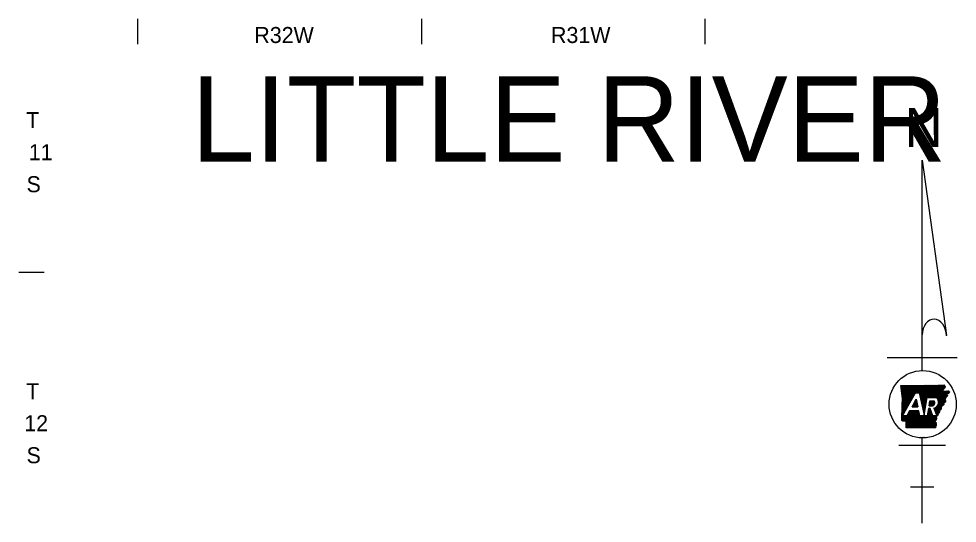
# Model space of a CAD drawing. Extents: x -17742 to 32032, y -17264 to 5867.
# Drawn here: x 27246 to 30763, y 3876 to 5766 of the extents above; entities that cross this region are included whole.
import ezdxf

# ---------------------------------------------------------------- set-up
doc = ezdxf.new("R2010")
doc.units = 0
for name, color, linetype in [('2', 7, 'Continuous'), ('Default', 7, 'Continuous'), ('R_Annotation', 7, 'Continuous')]:
    doc.layers.add(name, color=color, linetype=linetype)

msp = doc.modelspace()

# ---------------------------------------------------------------- linework, layer by layer
at = {"layer": 'Default'}
for p, q in [((27691.2, 5765.9), (27691.2, 5670.9)), ((28755.6, 5765.9), (28755.6, 5670.9)), ((29817.5, 5765.9), (29817.5, 5670.9)), ((27340.7, 4814.8), (27245.7, 4814.8))]:
    msp.add_line(p, q, dxfattribs=at)
at = {"layer": 'R_Annotation'}
for p, q in [((30631.7, 5235.8), (30722.6, 4578.7)), ((30631.7, 4447.8), (30631.7, 5235.8)), ((30500.1, 4496.6), (30763.3, 4496.6)), ((30551.9, 4391.4), (30553, 4392.5)), ((30552.3, 4388.3), (30556.5, 4392.5)), ((30552.7, 4385.2), (30559.9, 4392.5)), ((30553.1, 4382.1), (30563.4, 4392.5)), ((30553.4, 4379), (30566.9, 4392.5)), ((30553.8, 4375.9), (30570.4, 4392.5)), ((30554.2, 4372.8), (30573.9, 4392.5)), ((30554.6, 4369.7), (30577.3, 4392.5)), ((30555, 4366.6), (30580.8, 4392.5)), ((30555.4, 4363.5), (30584.3, 4392.5)), ((30555.8, 4360.4), (30587.8, 4392.5)), ((30556.1, 4357.3), (30591.3, 4392.5)), ((30556.5, 4354.2), (30594.8, 4392.5)), ((30556.9, 4351.1), (30598.2, 4392.5)), ((30557, 4316.4), (30633.1, 4392.5)), ((30557.1, 4320), (30629.6, 4392.5)), ((30557.3, 4323.6), (30626.2, 4392.5)), ((30557.3, 4348), (30601.7, 4392.5)), ((30557.4, 4327.2), (30622.7, 4392.5)), ((30557.5, 4330.8), (30619.2, 4392.5)), ((30557.6, 4334.4), (30615.7, 4392.5)), ((30557.7, 4338), (30612.2, 4392.5)), ((30557.7, 4344.9), (30605.2, 4392.5)), ((30557.9, 4341.6), (30608.7, 4392.5)), ((30558.1, 4278.9), (30606.6, 4364.7)), ((30606.6, 4364.7), (30621.1, 4364.7)), ((30608.8, 4364.7), (30636.6, 4392.5)), ((30612.2, 4364.7), (30640.1, 4392.5)), ((30615.7, 4364.7), (30643.6, 4392.6)), ((30619.2, 4364.7), (30647.2, 4392.6)), ((30621.4, 4363.4), (30650.7, 4392.7)), ((30622, 4360.5), (30654.2, 4392.7)), ((30622.6, 4357.6), (30657.8, 4392.8)), ((30623.2, 4354.7), (30661.3, 4392.8)), ((30623.8, 4351.9), (30664.9, 4392.9)), ((30624.4, 4349), (30668.4, 4393)), ((30625.1, 4346.1), (30671.9, 4393)), ((30625.7, 4343.3), (30675.5, 4393.1)), ((30626.3, 4340.4), (30679, 4393.1)), ((30626.9, 4337.5), (30682.5, 4393.2)), ((30627.5, 4334.7), (30686.1, 4393.2)), ((30628.1, 4331.8), (30689.6, 4393.3)), ((30628.7, 4328.9), (30693.2, 4393.4)), ((30629.3, 4326.1), (30696.7, 4393.4)), ((30653.5, 4346.8), (30700.3, 4393.5)), ((30657, 4346.8), (30703.9, 4393.6)), ((30660.5, 4346.8), (30707.4, 4393.7)), ((30664, 4346.8), (30711, 4393.8)), ((30667.5, 4346.8), (30714.6, 4393.8)), ((30671, 4346.8), (30715.3, 4391.1)), ((30674.4, 4346.8), (30717, 4389.3)), ((30677.9, 4346.8), (30717.5, 4386.3)), ((30681.4, 4346.8), (30709.5, 4374.9)), ((30684.6, 4346.4), (30708.8, 4370.7)), ((30686.5, 4344.9), (30712.5, 4370.9)), ((30688.2, 4343.1), (30716.2, 4371.1)), ((30689.7, 4341.1), (30719.8, 4371.3)), ((30691, 4338.9), (30723.5, 4371.5)), ((30692, 4336.5), (30727.2, 4371.7)), ((30692.8, 4333.8), (30730.5, 4371.5)), ((30693.3, 4330.8), (30732.1, 4369.6)), ((30730.6, 4364.6), (30733.7, 4367.8)), ((30556.4, 4298.4), (30585.7, 4327.7)), ((30556.6, 4302), (30590.3, 4335.7)), ((30556.7, 4305.6), (30594.8, 4343.8)), ((30556.8, 4309.2), (30599.4, 4351.8)), ((30556.9, 4312.8), (30603.9, 4359.8)), ((30593.8, 4312.5), (30609.7, 4340.6)), ((30594, 4312.5), (30611.9, 4330.4)), ((30597.5, 4312.5), (30612.5, 4327.6)), ((30598.1, 4320.2), (30611.3, 4333.3)), ((30602.7, 4328.2), (30610.6, 4336.2)), ((30607.2, 4336.2), (30610, 4339)), ((30630, 4323.2), (30649.7, 4342.9)), ((30630.6, 4320.3), (30649, 4338.7)), ((30631.2, 4317.4), (30648.3, 4334.5)), ((30631.8, 4314.6), (30647.5, 4330.3)), ((30650.4, 4346.8), (30684.1, 4346.8)), ((30657.7, 4316.3), (30676.1, 4334.7)), ((30658.4, 4320.5), (30672.6, 4334.7)), ((30659.2, 4324.7), (30669.1, 4334.7)), ((30659.9, 4329), (30665.6, 4334.7)), ((30660.7, 4333.2), (30662.1, 4334.7)), ((30660.9, 4334.7), (30676.8, 4334.7)), ((30661.2, 4316.3), (30678, 4333.1)), ((30664.7, 4316.3), (30679.2, 4330.8)), ((30668.2, 4316.3), (30679.8, 4328)), ((30678.2, 4301.8), (30716.8, 4340.4)), ((30679.2, 4299.2), (30717.5, 4337.6)), ((30680.1, 4296.7), (30718.1, 4334.7)), ((30681, 4294.2), (30718.8, 4331.9)), ((30689.6, 4316.6), (30716.2, 4343.2)), ((30692.6, 4323.1), (30724.2, 4354.7)), ((30693.3, 4327.3), (30723.8, 4357.8)), ((30720.3, 4347.4), (30724.6, 4351.7)), ((30556, 4284), (30567.5, 4295.6)), ((30556.1, 4287.6), (30572.1, 4303.6)), ((30556.2, 4291.2), (30576.6, 4311.6)), ((30556.3, 4294.8), (30581.2, 4319.7)), ((30556.6, 4260.3), (30593.2, 4296.9)), ((30558.7, 4258.8), (30596.7, 4296.9)), ((30561.2, 4257.9), (30600.2, 4296.9)), ((30565.3, 4258.5), (30603.6, 4296.9)), ((30568.8, 4258.6), (30607.1, 4296.9)), ((30571.6, 4257.8), (30610.6, 4296.9)), ((30571.7, 4251), (30617.6, 4296.9)), ((30571.7, 4254.5), (30614.1, 4296.9)), ((30571.7, 4247.5), (30619.4, 4295.2)), ((30571.7, 4244), (30620, 4292.3)), ((30584.9, 4296.9), (30574.7, 4278.9)), ((30578.7, 4285.8), (30589.7, 4296.9)), ((30583.2, 4293.9), (30586.2, 4296.9)), ((30619.1, 4296.9), (30584.9, 4296.9)), ((30593.8, 4312.5), (30615.7, 4312.5)), ((30600.9, 4312.5), (30613.1, 4324.7)), ((30604.4, 4312.5), (30613.7, 4321.8)), ((30606.6, 4233.6), (30666.5, 4293.5)), ((30607.9, 4312.5), (30614.3, 4319)), ((30611.4, 4312.5), (30614.9, 4316.1)), ((30614.9, 4312.5), (30615.6, 4313.2)), ((30632.4, 4311.7), (30646.8, 4326.1)), ((30633, 4308.8), (30646.1, 4321.9)), ((30633.6, 4306), (30645.3, 4317.6)), ((30634.3, 4303.1), (30644.6, 4313.4)), ((30634.9, 4300.2), (30643.8, 4309.2)), ((30635.5, 4297.4), (30643.1, 4305)), ((30636.1, 4294.5), (30642.4, 4300.8)), ((30636.7, 4291.6), (30641.6, 4296.6)), ((30637.3, 4288.8), (30640.9, 4292.3)), ((30651.8, 4282.3), (30665.5, 4296)), ((30652.5, 4286.5), (30664.6, 4298.6)), ((30653.3, 4290.8), (30663.6, 4301.1)), ((30654, 4295), (30662.7, 4303.7)), ((30654.7, 4299.2), (30661.7, 4306.2)), ((30655.5, 4303.4), (30658.2, 4306.2)), ((30661.8, 4306.2), (30655.9, 4306.2)), ((30657.7, 4316.3), (30672.2, 4316.3)), ((30671.9, 4278.9), (30661.8, 4306.2)), ((30671.7, 4316.3), (30679.5, 4324.2)), ((30676.1, 4307.6), (30686.7, 4278.9)), ((30676.3, 4306.9), (30677.4, 4307.9)), ((30677.3, 4304.3), (30683.9, 4311)), ((30682, 4291.6), (30702.9, 4312.5)), ((30682.9, 4289.1), (30702.5, 4308.6)), ((30683.9, 4286.5), (30702.1, 4304.8)), ((30684.8, 4284), (30695.5, 4294.7)), ((30706.9, 4316.5), (30711.8, 4321.4)), ((30555.3, 4262.4), (30571.7, 4278.9)), ((30555.4, 4266), (30568.2, 4278.9)), ((30555.5, 4269.6), (30564.7, 4278.9)), ((30555.6, 4273.2), (30561.3, 4278.9)), ((30555.7, 4276.8), (30558.4, 4279.5)), ((30555.8, 4280.4), (30563, 4287.6)), ((30574.7, 4278.9), (30558.1, 4278.9)), ((30571.7, 4240.6), (30620.6, 4289.5)), ((30571.7, 4237.1), (30621.3, 4286.6)), ((30571.8, 4233.7), (30621.9, 4283.7)), ((30575.3, 4233.7), (30622.5, 4280.9)), ((30578.7, 4233.6), (30624, 4278.9)), ((30582.2, 4233.6), (30627.4, 4278.9)), ((30585.7, 4233.6), (30630.9, 4278.9)), ((30589.2, 4233.6), (30634.4, 4278.9)), ((30592.6, 4233.6), (30637.9, 4278.9)), ((30596.1, 4233.6), (30641.4, 4278.9)), ((30599.6, 4233.6), (30644.8, 4278.9)), ((30603.1, 4233.6), (30648.3, 4278.9)), ((30610, 4233.6), (30667.4, 4291)), ((30613.5, 4233.6), (30668.3, 4288.4)), ((30617, 4233.6), (30669.3, 4285.9)), ((30620.5, 4233.6), (30670.2, 4283.3)), ((30651.2, 4278.9), (30622.9, 4278.9)), ((30623.9, 4233.6), (30671.2, 4280.8)), ((30627.4, 4233.6), (30672.7, 4278.9)), ((30630.9, 4233.6), (30676.2, 4278.9)), ((30634.4, 4233.6), (30679.7, 4278.9)), ((30637.8, 4233.6), (30683.2, 4278.9)), ((30637.9, 4285.9), (30640.2, 4288.1)), ((30638.6, 4283), (30639.4, 4283.9)), ((30641.3, 4233.5), (30684.3, 4276.5)), ((30644.8, 4233.5), (30684.5, 4273.2)), ((30648.3, 4233.5), (30684.6, 4269.9)), ((30651.8, 4233.5), (30684.8, 4266.6)), ((30655.2, 4233.5), (30679.1, 4257.4)), ((30686.7, 4278.9), (30671.9, 4278.9)), ((30685.7, 4281.4), (30694, 4289.7)), ((30658.7, 4233.5), (30680.1, 4255)), ((30662.2, 4233.5), (30681.2, 4252.5)), ((30665.7, 4233.5), (30682.3, 4250.1)), ((30669.1, 4233.5), (30683.4, 4247.7)), ((30672.6, 4233.5), (30684.3, 4245.1)), ((30676.1, 4233.5), (30682.7, 4240.1)), ((30679.6, 4233.5), (30681.1, 4235)), ((30631.7, 3876), (30631.7, 4195.8)), ((30544, 4168.6), (30719.4, 4168.6)), ((30587.9, 4012.8), (30675.6, 4012.8))]:
    msp.add_line(p, q, dxfattribs=at)
for points in [[(30551.8, 4392.5), (30599.8, 4392.5), (30642, 4392.5), (30691.7, 4393.3), (30714.8, 4393.9)], [(30551.8, 4392.5), (30599.8, 4392.5), (30642, 4392.5), (30691.7, 4393.3), (30714.8, 4393.9)], [(30557.1, 4317.8), (30557.9, 4343.1), (30551.8, 4392.5)], [(30555.2, 4262.5), (30557.9, 4343.1), (30551.8, 4392.5)], [(30621.1, 4364.7), (30639, 4281.2), (30650.4, 4346.8)], [(30729.9, 4371.8), (30734, 4367.4), (30723.7, 4358.9), (30724.8, 4350.3), (30715.9, 4344.4), (30718.9, 4331.2), (30712.1, 4325), (30711.5, 4318.2), (30703.1, 4315.2), (30701.8, 4302.3), (30695.9, 4295.9), (30693, 4286.3), (30684.2, 4278.3), (30684.9, 4264.2), (30679, 4257.6), (30684.4, 4245.5), (30680.6, 4233.5)], [(30707.7, 4370.7), (30730.2, 4371.8)], [(30707.7, 4370.6), (30730.2, 4371.8)], [(30609.7, 4340.6), (30615.7, 4312.5)], [(30657.7, 4316.3), (30660.9, 4334.7)], [(30555.2, 4262.5), (30557.1, 4317.8)], [(30622.9, 4278.9), (30619.1, 4296.9)], [(30655.9, 4306.2), (30651.2, 4278.9)], [(30680.6, 4233.5), (30571.7, 4233.7), (30571.7, 4257.7)], [(30680.6, 4233.5), (30571.7, 4233.7), (30571.7, 4257.7)]]:
    msp.add_lwpolyline(points, dxfattribs=at)
for centre, major_axis, ratio, start_param, end_param in [((30677.2, 4577.3), (-1.9, 63.2), 0.719778, 4.712385, 7.768526), ((30668.7, 4326.9), (-11.1, 0), 0.999987, 1.887169, 3.90762), ((30671.6, 4328.9), (-21.8, 0), 0.999987, 1.777838, 4.099264)]:
    msp.add_ellipse(centre, major_axis=major_axis, ratio=ratio, start_param=start_param, end_param=end_param, dxfattribs=at)
msp.add_ellipse((30633.8, 4321.8), major_axis=(126, 0), ratio=0.999976, dxfattribs=at)
for points in [[(30714.8, 4393.9), (30714.9, 4392.5), (30715.3, 4391.9), (30715.4, 4390.6), (30715.9, 4390.1), (30716.8, 4389.5), (30717.5, 4388.7), (30717.7, 4387.7), (30717.5, 4386.6), (30717.4, 4385.5), (30717.3, 4384.4), (30717.1, 4383.6), (30716.4, 4382.8), (30715.7, 4382.3), (30715.1, 4381.7), (30714.7, 4381), (30713.9, 4380.3), (30713.1, 4379.5), (30712.5, 4378.9), (30711.9, 4378), (30711.6, 4377.1), (30710.9, 4376.5), (30710.3, 4375.9), (30709.6, 4375.1), (30709.3, 4374.3), (30708.6, 4373.4), (30708.5, 4372.5), (30708, 4371.8), (30708, 4371.6)], [(30714.8, 4393.9), (30714.9, 4392.5), (30715.3, 4391.9), (30715.4, 4390.6), (30715.9, 4390.1), (30716.8, 4389.5), (30717.5, 4388.7), (30717.7, 4387.7), (30717.5, 4386.6), (30717.4, 4385.5), (30717.3, 4384.5), (30717.1, 4383.5), (30716.4, 4382.8), (30715.7, 4382.3), (30715.1, 4381.6), (30714.7, 4381), (30713.9, 4380.3), (30713.1, 4379.5), (30712.5, 4378.9), (30711.9, 4378), (30711.6, 4377.1), (30710.9, 4376.5), (30710.4, 4375.9), (30709.6, 4375.1), (30709.3, 4374.3), (30708.6, 4373.4), (30708.5, 4372.5), (30708, 4371.7), (30708, 4371.6)], [(30729.9, 4371.8), (30730.2, 4371.8), (30731.2, 4370.7), (30731.7, 4369.8), (30732.3, 4369.3), (30733.1, 4369.1), (30733.6, 4368.4), (30734, 4367.6), (30733.8, 4367), (30733, 4366.9), (30732, 4366.8), (30731.2, 4366.8), (30730.4, 4366.2), (30731.1, 4365.4), (30732, 4364.7), (30732.2, 4363.9), (30731.7, 4363.1), (30730.8, 4362.7), (30729.8, 4362.3), (30729, 4361.6), (30728.6, 4360.9), (30727.7, 4360.6), (30726.8, 4360.4), (30725.9, 4360.3), (30725, 4360.1), (30724.1, 4359.6), (30723.7, 4358.9), (30723.8, 4357.8), (30723.8, 4356.6), (30724.7, 4356.2), (30725.6, 4356.2), (30726.4, 4355.8), (30726.3, 4355.1), (30725.7, 4354.3), (30725, 4353.6), (30724.2, 4353.3), (30723.5, 4352.7), (30723.8, 4352), (30724.4, 4351.6), (30724.9, 4350.9), (30724.8, 4350.3), (30724.1, 4349.9), (30723.3, 4350.1), (30722.7, 4350.8), (30722.1, 4351), (30721.5, 4351.3), (30720.9, 4350.9), (30720.9, 4350.1), (30720.6, 4349.1), (30720.8, 4348.5), (30721.1, 4347.5), (30721.1, 4346.8), (30720.8, 4345.8), (30720.3, 4344.7), (30719.8, 4344.4), (30719.5, 4345.5), (30719.4, 4346.5), (30719, 4347), (30718.5, 4347), (30717.9, 4346.6), (30717.3, 4345.9), (30716.4, 4345.1), (30715.9, 4344.4), (30716.2, 4343.5), (30716.8, 4343.3), (30717.3, 4343.4), (30717.6, 4344), (30718, 4344.1), (30718.5, 4343.2)], [(30718.5, 4343.2), (30718.7, 4342.3), (30718.2, 4341.4), (30718, 4340.5), (30718, 4339.6), (30717.1, 4339.1), (30716.3, 4338.5), (30716.8, 4337.7), (30717.7, 4337.1), (30718.5, 4336.6), (30719.1, 4336.1), (30719.3, 4334.9), (30719.4, 4334.1), (30719.7, 4333), (30719.8, 4332.3), (30719.3, 4331.4), (30718.7, 4331.2), (30718, 4331.4), (30717.3, 4331.5), (30716.6, 4330.9), (30716.2, 4330.1), (30715.7, 4329.2), (30715.4, 4328.5), (30715.1, 4327.7), (30714.4, 4326.8), (30713.6, 4326.7), (30712.7, 4326.5), (30712.1, 4325.8), (30712.2, 4324.7), (30712.7, 4324), (30713.1, 4323.1), (30713.4, 4322.2), (30713.3, 4321.2), (30712.9, 4320.5), (30712.4, 4320), (30712.1, 4319.1), (30711.7, 4318.4), (30711.4, 4318.1), (30710.7, 4318.2), (30709.9, 4318.3), (30709.2, 4318.3), (30708.6, 4318), (30708, 4318.2), (30707.3, 4318.9), (30706.8, 4319.4), (30706.2, 4319.6), (30705.6, 4319.3), (30705.5, 4318.3), (30705.8, 4317.3), (30706, 4315.9), (30705.8, 4315.1), (30705.7, 4313.7)], [(30705.7, 4313.7), (30704.6, 4313), (30704.2, 4312.1), (30701.5, 4312.4), (30701.6, 4311.4), (30700.6, 4310.9), (30699.8, 4310.3), (30700.3, 4309.6), (30701.2, 4309), (30702.1, 4308.5), (30702.6, 4308), (30702.8, 4306.7), (30702.9, 4306), (30703.2, 4304.9), (30703.3, 4304.2), (30702.8, 4303.3), (30702.2, 4303.1), (30701.5, 4303.3), (30700.8, 4303.4), (30700.1, 4302.8), (30699.7, 4301.9), (30699.3, 4301.1), (30698.9, 4300.4), (30698.6, 4299.6), (30697.9, 4298.7), (30697.2, 4298.6), (30696.2, 4298.3), (30695.6, 4297.7), (30695.7, 4296.6), (30696.2, 4295.9), (30696.7, 4294.9), (30696.9, 4294.1), (30696.8, 4293.1), (30696.4, 4292.4), (30695.9, 4291.9), (30695.6, 4291), (30695.2, 4290.2), (30694.9, 4290), (30694.2, 4290.1), (30693.4, 4290.2), (30692.7, 4290.2), (30692.1, 4289.8), (30691.5, 4290.1), (30690.8, 4290.8), (30690.3, 4291.3), (30689.7, 4291.5), (30689.1, 4291.2), (30689, 4290.2), (30689.3, 4289.2), (30689.5, 4287.8), (30689.3, 4287), (30689.2, 4285.6)], [(30571.7, 4257.7), (30571.8, 4257.6), (30571.2, 4258), (30570.5, 4258.4), (30569.6, 4258.5), (30568.5, 4258.6), (30567.6, 4258.7), (30566.6, 4259.3), (30565.6, 4258.7), (30564.5, 4258.2), (30563.8, 4258.8), (30563, 4258.4), (30562.4, 4258.6), (30561.3, 4257.8), (30560.3, 4258.1), (30559.6, 4257.9), (30558.8, 4257.9), (30558.6, 4259), (30557.7, 4259.1), (30557, 4259.5), (30556.5, 4260.5), (30556.1, 4261.4), (30555.2, 4262.5)], [(30571.7, 4257.7), (30571.8, 4257.6), (30571.2, 4258), (30570.5, 4258.4), (30569.6, 4258.5), (30568.5, 4258.6), (30567.6, 4258.7), (30566.6, 4259.3), (30565.6, 4258.7), (30564.5, 4258.2), (30563.8, 4258.7), (30563, 4258.4), (30562.4, 4258.6), (30561.3, 4257.8), (30560.4, 4258.1), (30559.6, 4257.9), (30558.7, 4257.9), (30558.6, 4258.9), (30557.7, 4259.1), (30557, 4259.5), (30556.5, 4260.6), (30556.1, 4261.4), (30555.2, 4262.5)], [(30685.2, 4274.4), (30684.9, 4273.7), (30684.5, 4272.6), (30684.6, 4271.6), (30685.1, 4270.7), (30685.8, 4270.2), (30686.6, 4269.5), (30686.5, 4268.5), (30686.1, 4268.1), (30685, 4268.4), (30684.2, 4268.7), (30683.5, 4268.5), (30682.6, 4268.1), (30681.9, 4268), (30682, 4266.5), (30682.9, 4265.5), (30683.7, 4265.5), (30684.6, 4265.4), (30684.9, 4264.4), (30684.4, 4263.5), (30683.5, 4263), (30682.4, 4263.6), (30681.6, 4264.1), (30680.8, 4264.7), (30679.8, 4264.9), (30679.2, 4264.8), (30678.9, 4263.6), (30679.4, 4262.4), (30680.2, 4261.6), (30680.9, 4260.6), (30680.8, 4259.9), (30680.3, 4259.7), (30679.3, 4259.5), (30678.7, 4259.2), (30678.6, 4259), (30678.9, 4257.9), (30679.1, 4256.8), (30679.1, 4256), (30678.8, 4255.3), (30678.3, 4254.1), (30678.4, 4253.3), (30678.7, 4252.9), (30679.2, 4253), (30679.8, 4253.4), (30680.2, 4253.9), (30680.5, 4254.5), (30681.1, 4255), (30681.9, 4254.6), (30682.1, 4253.7), (30681.6, 4252.9), (30681, 4252.5), (30680.2, 4252.2), (30679.7, 4251.6), (30679.8, 4250.8), (30680.3, 4250.4), (30681.4, 4250.6), (30682.1, 4250.9), (30682.5, 4251.3), (30683, 4251.8), (30683.3, 4252.3), (30683.7, 4252.9), (30684.4, 4253), (30684.7, 4252.6), (30684.5, 4251.6), (30684.1, 4250.6), (30683.6, 4249.8), (30683, 4249.2), (30682.2, 4248), (30682.3, 4246.9), (30682.6, 4245.9), (30683, 4245.3), (30683.8, 4245.4), (30684.5, 4245.5), (30685, 4245.1), (30685, 4244.3), (30684.4, 4243.4), (30683.8, 4242.7), (30683.5, 4241.6), (30683.6, 4240.9), (30683.6, 4240.2), (30683.4, 4239.4), (30683, 4239), (30681.9, 4239), (30680.7, 4239.2), (30680.1, 4238.8), (30680.2, 4237.8), (30680.9, 4237.1), (30681.4, 4236.7), (30682.1, 4235.9), (30682.4, 4235.2), (30682.3, 4234.6), (30681.8, 4234.1), (30680.6, 4233.5)], [(30685.2, 4274.4), (30684.9, 4273.7), (30684.5, 4272.6), (30684.6, 4271.6), (30685.1, 4270.7), (30685.8, 4270.2), (30686.6, 4269.5), (30686.5, 4268.5), (30686.1, 4268.1), (30685, 4268.4), (30684.2, 4268.7), (30683.5, 4268.5), (30682.6, 4268.1), (30681.9, 4268), (30682, 4266.5), (30682.9, 4265.5), (30683.7, 4265.5), (30684.6, 4265.4), (30684.9, 4264.4), (30684.4, 4263.5), (30683.5, 4263), (30682.4, 4263.6), (30681.6, 4264.1), (30680.8, 4264.7), (30679.8, 4264.9), (30679.2, 4264.8), (30678.9, 4263.6), (30679.4, 4262.4), (30680.2, 4261.6), (30680.9, 4260.6), (30680.8, 4259.9), (30680.3, 4259.7), (30679.3, 4259.5), (30678.7, 4259.2), (30678.6, 4259), (30678.9, 4257.9), (30679.1, 4256.8), (30679.1, 4256), (30678.8, 4255.3), (30678.3, 4254.1), (30678.4, 4253.3), (30678.7, 4252.9), (30679.2, 4253), (30679.8, 4253.4), (30680.2, 4253.9), (30680.5, 4254.5), (30681.1, 4255), (30681.9, 4254.6), (30682.1, 4253.7), (30681.6, 4252.9), (30681, 4252.5), (30680.2, 4252.2), (30679.7, 4251.6), (30679.8, 4250.8), (30680.3, 4250.4), (30681.4, 4250.6), (30682.1, 4250.9), (30682.5, 4251.3), (30683, 4251.8), (30683.3, 4252.3), (30683.7, 4252.9), (30684.4, 4253), (30684.7, 4252.6), (30684.5, 4251.6), (30684.1, 4250.6), (30683.6, 4249.8), (30683, 4249.2), (30682.2, 4248), (30682.3, 4246.9), (30682.6, 4245.9), (30683, 4245.3), (30683.8, 4245.4), (30684.5, 4245.5), (30685, 4245.1), (30685, 4244.3), (30684.4, 4243.4), (30683.8, 4242.7), (30683.5, 4241.6), (30683.6, 4240.9), (30683.6, 4240.2), (30683.4, 4239.4), (30683, 4239), (30681.9, 4239), (30680.7, 4239.2), (30680.1, 4238.8), (30680.2, 4237.8), (30680.9, 4237.1), (30681.4, 4236.7), (30682.1, 4235.9), (30682.4, 4235.2), (30682.3, 4234.6), (30681.8, 4234.1), (30680.6, 4233.5)], [(30689.2, 4285.6), (30689.1, 4285.6), (30688.6, 4284.9), (30688.9, 4283.8), (30690, 4283.4), (30690.6, 4282.4), (30690.6, 4281.5), (30690.2, 4280.3), (30689.7, 4279.7), (30688.6, 4279.5), (30687.8, 4279.4), (30687.7, 4278), (30687.4, 4277.3), (30686.7, 4277.1), (30685.8, 4277.6), (30685.3, 4277.8), (30684.6, 4278.1), (30683.8, 4278.5), (30683.2, 4278.5), (30683.4, 4277.2), (30683.4, 4277.1), (30684.1, 4276.1), (30684.8, 4275.3), (30685.2, 4274.4)], [(30689.2, 4285.6), (30689.1, 4285.6), (30688.6, 4284.9), (30688.9, 4283.8), (30690, 4283.4), (30690.6, 4282.4), (30690.6, 4281.5), (30690.2, 4280.3), (30689.7, 4279.7), (30688.6, 4279.5), (30687.8, 4279.4), (30687.7, 4278), (30687.4, 4277.3), (30686.7, 4277.1), (30685.8, 4277.6), (30685.3, 4277.8), (30684.6, 4278.1), (30683.8, 4278.5), (30683.2, 4278.5), (30683.4, 4277.2), (30683.4, 4277.1), (30684.1, 4276.1), (30684.8, 4275.3), (30685.2, 4274.4)]]:
    msp.add_spline(points, degree=3, dxfattribs=at)

# ---------------------------------------------------------------- texts
at = {"layer": '2'}
for s, height, p in [('R32W', 60, (28128.6, 5675.1)), ('R31W', 60, (29240.6, 5675.1)), ('LITTLE RIVER', 320, (27892.8, 5230.5)), ('T', 60, (27273.6, 5356.1)), ('11', 60, (27283.3, 5236.1)), ('S', 60, (27274.8, 5116.1)), ('T', 60, (27273.6, 4340.7)), ('12', 60, (27266.3, 4220.7)), ('S', 60, (27274.8, 4100.7))]:
    msp.add_text(s, height=height, dxfattribs=at).set_placement(p)
at = {"layer": 'R_Annotation'}
for s, height, p in [('N', 146.7, (30566.3, 5285.4)), ('STS 10-03-17', 3.644, (30621.7, 4196.8))]:
    msp.add_text(s, height=height, dxfattribs=at).set_placement(p)

doc.saveas('drawing.dxf')
